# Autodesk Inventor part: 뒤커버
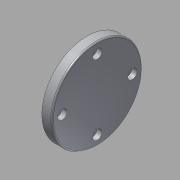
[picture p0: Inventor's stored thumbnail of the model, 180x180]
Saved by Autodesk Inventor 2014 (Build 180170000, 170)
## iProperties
Created: 2015-09
Part Number: 뒤커버
Material: 알루미늄 6061
Document SubType Name: Modeling
Designer: mduedu
Density: 1 g/cm^3
Appearance: 알루미늄 - 평지
Author: mduedu
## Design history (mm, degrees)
sketch "스케치1"
  geometry: L1 (-15.5, 47)-(-15.5, 78); L2 (-15.5, 78)-(-22.5, 78); L3 (-22.5, 78)-(-22.5, 67); L4 (-25.5, 67)-(-25.5, 47); L5 (-79.5, 39.5)-(-79.5, 54.5) reference; L6 (48.5, 54.5)-(48.5, 39.5) reference; L7 (-79.5, 47)-(48.5, 47); L8 (-22.5, 67)-(-25.5, 67); L9 (-25.5, 47)-(-15.5, 47); 1 further point
  constraints: 14 end point, 4 midpoint, 3 parallel, 1 collinear, 1 point on line, 1 vertical
  dimensions: "d6" = 62 diameter of L2 L7; "d7" = 7 distance of L1.end L2.end; "d8" = 40 diameter of L3.end L7; "d32" = 10 distance between parallel lines of L1 L4
revolve "회전1" sketch "스케치1" stored, may be unused: angle "d4" = 90 deg
sketch "스케치4"
  geometry: C1 r 31 at (0, 0) reference; 2 further points
  constraints: 1 coincident
hole "구멍3" sketch "스케치4" at (0, 0) diameter "d33" = 33; stored, may be unused: countersink angle "d37" = 90 deg, drill point angle "d39" = 0 deg; dims "d34" = 6, "d35" = 4, "d36" = 2, "d38" = 5
fillet "모깎기4" dims "d40" = 1
chamfer "모따기2" distance "d41" = 1; stored, may be unused: second distance "d42" = 2, angle "d43" = 45 deg
sketch "스케치5" dims "d44" = 48
  geometry: C1 r 31 at (0, 0) reference; 6 further points
  constraints: 2 vertical alignment, 1 coincident, 7 other
  dimensions: "d47" = 360 deg dimension on C1.centre point (0, -24) (derived)
sketch "스케치6"
  geometry: 4 further points
hole "구멍4" sketch "스케치6" at (24, 0), (0, 24), (-24, 0), (0, -24) diameter "d49" = 3.4; stored, may be unused: countersink angle "d53" = 90 deg, drill point angle "d55" = 0 deg; dims "d50" = 6, "d51" = 6.5, "d52" = 3.4, "d54" = 8
node "솔리드1"
node "참조1"
node "참조2"
